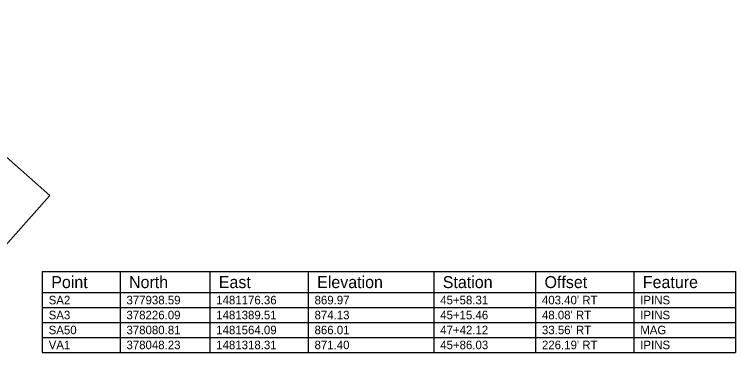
# Model space of a CAD drawing. Extents: x 1475580 to 1482245, y 377937 to 382467.
# Drawn here: x 1481823.7 to 1482245.4, y 378184 to 378385.3 of the extents above; entities that cross this region are included whole.
import ezdxf

# ---------------------------------------------------------------- set-up
doc = ezdxf.new("R2010")
doc.units = 0
doc.layers.add('Default', color=7, linetype='Continuous')

msp = doc.modelspace()

# ---------------------------------------------------------------- linework, layer by layer
at = {"layer": 'Default'}
for p, q in [((1481724.54, 378385.33), (1481844.42, 378279.37)), ((1481759.22, 378184), (1481844.42, 378279.37)), ((1481839.95, 378234.86), (1482245.45, 378234.86)), ((1481839.95, 378234.86), (1481839.95, 378187.61)), ((1481885.45, 378234.86), (1481885.45, 378187.61)), ((1481937.95, 378234.86), (1481937.95, 378187.61)), ((1481995.45, 378234.86), (1481995.45, 378187.61)), ((1482068.95, 378234.86), (1482068.95, 378187.61)), ((1482128.45, 378234.86), (1482128.45, 378187.61)), ((1482185.95, 378234.86), (1482185.95, 378187.61)), ((1482245.45, 378234.86), (1482245.45, 378187.61)), ((1482245.45, 378234.86), (1482245.45, 378187.61)), ((1481839.95, 378222.61), (1482245.45, 378222.61)), ((1481839.95, 378213.86), (1482245.45, 378213.86)), ((1481839.95, 378213.86), (1482245.45, 378213.86)), ((1481839.95, 378213.86), (1482245.45, 378213.86)), ((1481839.95, 378213.86), (1482245.45, 378213.86)), ((1481839.95, 378213.86), (1482245.45, 378213.86)), ((1481839.95, 378213.86), (1482245.45, 378213.86)), ((1481839.95, 378213.86), (1482245.45, 378213.86)), ((1481839.95, 378205.11), (1482245.45, 378205.11)), ((1481839.95, 378205.11), (1482245.45, 378205.11)), ((1481839.95, 378205.11), (1482245.45, 378205.11)), ((1481839.95, 378205.11), (1482245.45, 378205.11)), ((1481839.95, 378205.11), (1482245.45, 378205.11)), ((1481839.95, 378205.11), (1482245.45, 378205.11)), ((1481839.95, 378205.11), (1482245.45, 378205.11)), ((1481839.95, 378196.36), (1482245.45, 378196.36)), ((1481839.95, 378196.36), (1482245.45, 378196.36)), ((1481839.95, 378196.36), (1482245.45, 378196.36)), ((1481839.95, 378196.36), (1482245.45, 378196.36)), ((1481839.95, 378196.36), (1482245.45, 378196.36)), ((1481839.95, 378196.36), (1482245.45, 378196.36)), ((1481839.95, 378196.36), (1482245.45, 378196.36)), ((1481839.95, 378187.61), (1482245.45, 378187.61)), ((1481839.95, 378187.61), (1482245.45, 378187.61)), ((1481839.95, 378187.61), (1482245.45, 378187.61)), ((1481839.95, 378187.61), (1482245.45, 378187.61)), ((1481839.95, 378187.61), (1482245.45, 378187.61)), ((1481839.95, 378187.61), (1482245.45, 378187.61)), ((1481839.95, 378187.61), (1482245.45, 378187.61))]:
    msp.add_line(p, q, dxfattribs=at)

# ---------------------------------------------------------------- texts
for s, height, p in [('Point', 7, (1481845.2, 378225.23)), ('North', 7, (1481890.7, 378225.23)), ('East', 7, (1481943.2, 378225.23)), ('Elevation', 7, (1482000.7, 378225.23)), ('Station', 7, (1482074.2, 378225.23)), ('Offset', 7, (1482133.7, 378225.23)), ('Feature', 7, (1482191.2, 378225.23)), ('SA2', 5, (1481843.7, 378215.73)), ('377938.59', 5, (1481889.2, 378215.73)), ('1481176.36', 5, (1481941.7, 378215.73)), ('869.97', 5, (1481999.2, 378215.73)), ('45+58.31', 5, (1482072.7, 378215.73)), ("403.40' RT", 5, (1482132.2, 378215.73)), ('IPINS', 5, (1482189.7, 378215.73)), ('SA3', 5, (1481843.7, 378206.98)), ('378226.09', 5, (1481889.2, 378206.98)), ('1481389.51', 5, (1481941.7, 378206.98)), ('874.13', 5, (1481999.2, 378206.98)), ('45+15.46', 5, (1482072.7, 378206.98)), ("48.08' RT", 5, (1482132.2, 378206.98)), ('IPINS', 5, (1482189.7, 378206.98)), ('SA50', 5, (1481843.7, 378198.23)), ('378080.81', 5, (1481889.2, 378198.23)), ('1481564.09', 5, (1481941.7, 378198.23)), ('866.01', 5, (1481999.2, 378198.23)), ('47+42.12', 5, (1482072.7, 378198.23)), ("33.56' RT", 5, (1482132.2, 378198.23)), ('MAG', 5, (1482189.7, 378198.23)), ('VA1', 5, (1481843.7, 378189.48)), ('378048.23', 5, (1481889.2, 378189.48)), ('1481318.31', 5, (1481941.7, 378189.48)), ('871.40', 5, (1481999.2, 378189.48)), ('45+86.03', 5, (1482072.7, 378189.48)), ("226.19' RT", 5, (1482132.2, 378189.48)), ('IPINS', 5, (1482189.7, 378189.48))]:
    msp.add_text(s, height=height, dxfattribs=at).set_placement(p)

doc.saveas('drawing.dxf')
